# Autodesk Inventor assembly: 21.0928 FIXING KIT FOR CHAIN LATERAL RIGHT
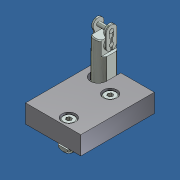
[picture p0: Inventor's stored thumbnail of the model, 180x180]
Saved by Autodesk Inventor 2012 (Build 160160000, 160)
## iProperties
Created: 2013-11
Part Number: 21.0928 FIXING KIT FOR CHAIN LATERAL RIGHT
Document SubType Name: Assembly
Designer: Admin
Author: Admin
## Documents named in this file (8)
- C:\Andys Backup Data\ANDY'S INVENTOR\INVENTOR LIBRARIES\PARTS LIBRARY\COUNTER WEIGHT SYSTEM HEAVY\21.0928 FIXING KIT FOR CHAIN LATERAL RIGHT.iam
- C:\Andys Backup Data\ANDY'S INVENTOR\INVENTOR LIBRARIES\PARTS LIBRARY\COUNTER WEIGHT SYSTEM HEAVY\SUBCOMPONENTS\21.0928 FIXING KIT FOR CHAIN LATERAL.ipt
- C:\Andys Backup Data\ANDY'S INVENTOR\INVENTOR LIBRARIES\PARTS LIBRARY\COUNTER WEIGHT SYSTEM HEAVY\SUBCOMPONENTS\21.0925 CHAIN CLAMPING DEVICE S.ipt
- C:\Andys Backup Data\ANDY'S INVENTOR\INVENTOR LIBRARIES\PARTS LIBRARY\FASTENING ELEMENTS\SCREWS CAP\21.1249 M10X25.ipt
- C:\Andys Backup Data\ANDY'S INVENTOR\INVENTOR LIBRARIES\PARTS LIBRARY\FASTENING ELEMENTS\SCREWS CAP\21.1206 M8X30.ipt
- C:\Andys Backup Data\ANDY'S INVENTOR\INVENTOR LIBRARIES\PARTS LIBRARY\FASTENING ELEMENTS\SCREWS CAP\21.1204 M8X25.ipt
- C:\Andys Backup Data\ANDY'S INVENTOR\INVENTOR LIBRARIES\PARTS LIBRARY\FASTENING ELEMENTS\NUTS\21.1351 M8 SQUARE NUT.ipt
- C:\Andys Backup Data\ANDY'S INVENTOR\INVENTOR LIBRARIES\PARTS LIBRARY\COUNTER WEIGHT SYSTEM HEAVY\29.0308 CONNECTING LINK 08B.iam
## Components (7 placed, 7 different names)
1. 21.0928 FIXING KIT FOR CHAIN LATERAL:1 — Insert:1, Angle:1, Insert:2, Angle:2, Insert:3, Insert:4, Insert:5, Angle:3
2. 21.0925 CHAIN CLAMPING DEVICE S:2 — Insert:1, Angle:1, Mate:1, Mate:2
3. 29.0308 CONNECTING LINK 08B:2 [sub-assembly] — Mate:1, Mate:2, Angle:2
4. 21.1204  M8 x 25:2 — Insert:4
5. 21.1206 M8 x 30:2 — Insert:3
6. 21.1351 M8 SQUARE NUT:2 — Insert:5, Angle:3
7. 21.1249 M10 X 25:2 — Insert:2
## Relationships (10: Insert 5, Angle 3, Mate 2)
- Insert:1: 21.0928 FIXING KIT FOR CHAIN LATERAL:1 ↔ 21.0925 CHAIN CLAMPING DEVICE S:2
- Angle:1: 21.0928 FIXING KIT FOR CHAIN LATERAL:1 ↔ 21.0925 CHAIN CLAMPING DEVICE S:2
- Insert:2: 21.0928 FIXING KIT FOR CHAIN LATERAL:1 ↔ 21.1249 M10 X 25:2
- Mate:1: 21.0925 CHAIN CLAMPING DEVICE S:2 ↔ 29.0308 CONNECTING LINK 08B:2
- Mate:2: 21.0925 CHAIN CLAMPING DEVICE S:2 ↔ 29.0308 CONNECTING LINK 08B:2
- Angle:2: 21.0928 FIXING KIT FOR CHAIN LATERAL:1 ↔ 29.0308 CONNECTING LINK 08B:2
- Insert:3: 21.0928 FIXING KIT FOR CHAIN LATERAL:1 ↔ 21.1206 M8 x 30:2
- Insert:4: 21.0928 FIXING KIT FOR CHAIN LATERAL:1 ↔ 21.1204  M8 x 25:2
- Insert:5: 21.0928 FIXING KIT FOR CHAIN LATERAL:1 ↔ 21.1351 M8 SQUARE NUT:2
- Angle:3: 21.0928 FIXING KIT FOR CHAIN LATERAL:1 ↔ 21.1351 M8 SQUARE NUT:2
